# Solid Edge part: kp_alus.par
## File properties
Author: Georg
Template: Iso Metric Part.par
Last saved by: Georg
Revision: 4
Application: Solid Edge
Accuracy: 0,990
Face Style: Model Default
Fill Style: Normal
Coef. of Thermal Exp: 0.0
Thermal Conductivity: 0.0
Specific Heat: 0.0
Modulus of Elasticity: 0.0
Poisson's Ratio: 0.0
Yield Stress: 0.0
Ultimate Stress: 0.0
Elongation: 0.0
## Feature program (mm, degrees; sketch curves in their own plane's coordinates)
sketch for "ExtrudedProtrusion_1" plane through (0, 0, -150) normal (0, 0, 1) x-axis (1, 0, 0)
  circle centre (0, 4420.2777) radius 25
extrude "ExtrudedProtrusion_1" add finite 30 along -normal
sketch for "ExtrudedProtrusion_2" plane through (0, 4420.2777, -180) normal (0, 0, -1) x-axis (0, -1, 0)
  circle centre (0, 0) radius 100
extrude "ExtrudedProtrusion_2" add finite 10 along +normal
sketch for "ExtrudedCutout_1" #1 plane through (0, 4420.2777, -190) normal (0, 0, -1) x-axis (0, -1, 0)
  line (-57.5, 31.78) -> (57.5, 31.78)
  line (57.5, 31.78) -> (57.5, 71.78)
  line (57.5, 71.78) -> (-57.5, 71.78)
  line (-57.5, 71.78) -> (-57.5, 31.78)
  dimension (linear) = 57.5
  dimension (linear) = 57.5
sketch for "ExtrudedCutout_1" #2 plane through (0, 4420.2777, -190) normal (0, 0, -1) x-axis (0, -1, 0)
  line (-57.5, -31.78) -> (57.5, -31.78)
  line (57.5, -31.78) -> (57.5, -71.78)
  line (57.5, -71.78) -> (-57.5, -71.78)
  line (-57.5, -71.78) -> (-57.5, -31.78)
extrude "ExtrudedCutout_1" cut finite 5 along -normal
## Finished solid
Body 1: solid body, 15 faces, 28 edges, 16 vertices.
  Faces by surface: plane 13, cylinder 2
  Edges by curve: line 24, circle 4
Bounding box of the edges (mm): 200.000 x 200.000 x 40.000, from (-100, 4320.2777, -190) to (100, 4520.2777, -150).
Cylindrical faces by radius (mm): R25 x1, R100 x1
Planar faces by outward normal: +x 2, +y 2, +z 2, -x 2, -y 2, -z 3
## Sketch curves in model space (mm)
circle centre (0, 4420.2777, -150) radius 25
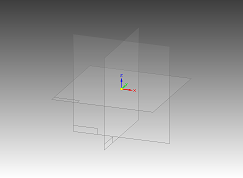
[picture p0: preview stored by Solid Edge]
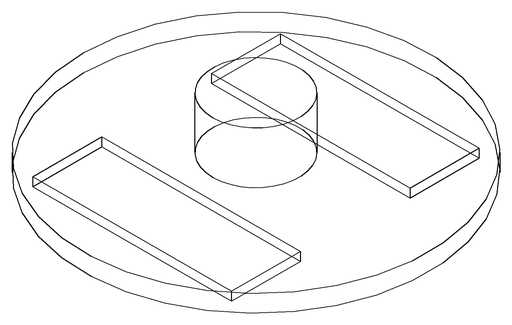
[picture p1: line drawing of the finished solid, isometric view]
